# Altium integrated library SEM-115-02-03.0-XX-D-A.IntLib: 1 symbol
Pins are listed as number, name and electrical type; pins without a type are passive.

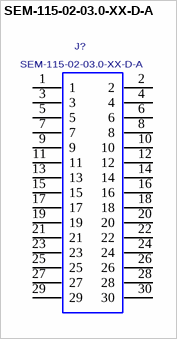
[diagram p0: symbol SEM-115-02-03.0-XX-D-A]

## SEM-115-02-03.0-XX-D-A
designator J?
0.8 MM TIGER EYE MICRO SOCKET,30 PINS.; MANUFACTURER: SAMTEC
footprint SEM-115-02-03.0-XX-D-A
pins: 1, 2, 3, 4, 5, 6, 7, 8, 9, 10, 11, 12, 13, 14, 15, 16, 17, 18, 19, 20, 21, 22, 23, 24, 25, 26, 27, 28, 29, 30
